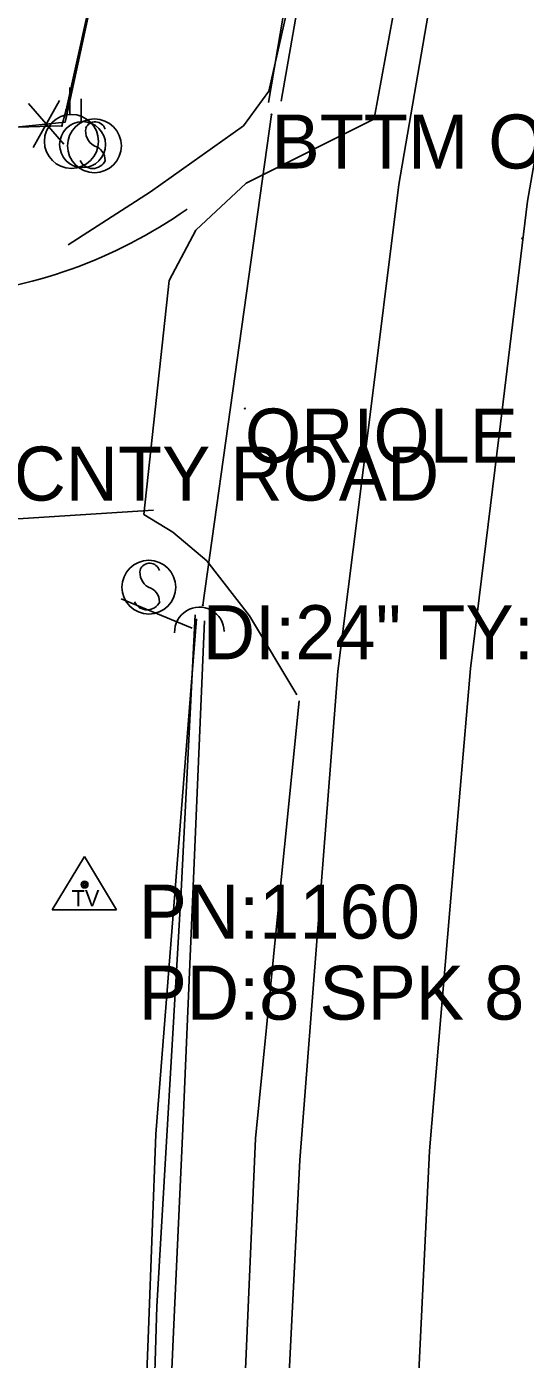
# Model space of a CAD drawing. Extents: x 954793 to 988390, y 1867850 to 1924428.
# Drawn here: x 960952.9 to 960999.1, y 1905465.6 to 1905589 of the extents above; entities that cross this region are included whole.
import ezdxf

# ---------------------------------------------------------------- set-up
doc = ezdxf.new("R2010")
doc.units = 0
for name, color, linetype in [('S_CROSS_DRAIN', 7, 'Continuous'), ('S_DITCHLINE', 7, 'Continuous'), ('S_DRG_PT_SYM', 7, 'Continuous'), ('S_DRIVEWAY', 7, 'Continuous'), ('S_EDGE_PAVEMENT', 7, 'Continuous'), ('S_FENCE', 7, 'Continuous'), ('S_GRAVEL_ROAD', 7, 'Continuous'), ('S_GRD_PT_SYM', 7, 'Continuous'), ('S_MSC_PT_SYM', 7, 'Continuous'), ('S_PAVEMENT_CROWN', 7, 'Continuous'), ('S_SECONDARY_CTL', 7, 'Continuous'), ('S_SECONDARY_CTL_ANNOT', 7, 'Continuous'), ('S_SHOULDER', 7, 'Continuous'), ('S_SIDE_DRAIN', 7, 'Continuous'), ('S_SIDE_DRAIN_ANNOT', 7, 'Continuous'), ('S_SIGN', 7, 'Continuous'), ('S_STREAM', 7, 'Continuous'), ('S_SURVEY_TEXT_ANNOT', 7, 'Continuous'), ('S_UTILITY_POLE', 7, 'Continuous'), ('S_UTL_PT_SYM', 7, 'Continuous')]:
    doc.layers.add(name, color=color, linetype=linetype)

msp = doc.modelspace()

# ---------------------------------------------------------------- linework, layer by layer
at = {"layer": 'S_CROSS_DRAIN'}
msp.add_arc((960968.9, 1905532.93), 2.3, 1.1524, 181.4816, dxfattribs=at)
at = {"layer": 'S_DITCHLINE'}
for points in [[(960975.29, 1905581.95), (960977.49, 1905594.88), (960979.69, 1905607.8), (960982.5, 1905621.27), (960985.31, 1905634.74), (960988.11, 1905648.21), (960990.92, 1905661.68)], [(960976.47, 1905582.09), (960978.64, 1905594.66), (960980.81, 1905607.22), (960983.9, 1905620.71), (960986.99, 1905634.2), (960990.08, 1905647.69), (960993.16, 1905661.18)], [(960962.25, 1905289.04), (960962.35, 1905306.2), (960962.45, 1905323.37), (960962.55, 1905340.53), (960962.65, 1905357.7), (960962.51, 1905371.75), (960962.38, 1905385.8), (960962.24, 1905399.85), (960962.1, 1905413.9), (960962.8, 1905432.03), (960963.49, 1905450.16), (960964.19, 1905468.29), (960964.88, 1905486.43), (960966.76, 1905510.29), (960968.63, 1905534.15)], [(960964.36, 1905253.1), (960964.62, 1905271.14), (960964.88, 1905289.19), (960965.02, 1905306.4), (960965.15, 1905323.62), (960965.29, 1905340.84), (960965.42, 1905358.06), (960965.09, 1905371.99), (960964.76, 1905385.92), (960964.43, 1905399.86), (960964.1, 1905413.79), (960964.91, 1905431.9), (960965.71, 1905450.02), (960966.51, 1905468.14), (960967.32, 1905486.25), (960968.34, 1905510.11), (960969.37, 1905533.98)]]:
    msp.add_lwpolyline(points, dxfattribs=at)
at = {"layer": 'S_DRG_PT_SYM'}
for points in [[(960975.57, 1905580.85), (960975.52, 1905580.85), (960975.57, 1905580.85), (960975.56, 1905580.8), (960975.57, 1905580.85), (960975.62, 1905580.84), (960975.57, 1905580.85), (960975.58, 1905580.9)], [(960975.57, 1905580.85), (960975.52, 1905580.85), (960975.57, 1905580.85), (960975.56, 1905580.8), (960975.57, 1905580.85), (960975.62, 1905580.84), (960975.57, 1905580.85), (960975.58, 1905580.9)], [(960969.22, 1905535.41), (960969.17, 1905535.42), (960969.22, 1905535.41), (960969.22, 1905535.36), (960969.22, 1905535.41), (960969.27, 1905535.4), (960969.22, 1905535.41), (960969.23, 1905535.46)], [(960969.22, 1905535.41), (960969.17, 1905535.42), (960969.22, 1905535.41), (960969.22, 1905535.36), (960969.22, 1905535.41), (960969.27, 1905535.4), (960969.22, 1905535.41), (960969.23, 1905535.46)]]:
    msp.add_lwpolyline(points, close=True, dxfattribs=at)
for points in [[(960975.57, 1905580.85), (960975.57, 1905580.9), (960975.57, 1905580.85), (960975.52, 1905580.85), (960975.57, 1905580.85), (960975.57, 1905580.8), (960975.57, 1905580.85), (960975.62, 1905580.85)], [(960969.22, 1905535.41), (960969.22, 1905535.46), (960969.22, 1905535.41), (960969.17, 1905535.41), (960969.22, 1905535.41), (960969.22, 1905535.36), (960969.22, 1905535.41), (960969.27, 1905535.41)]]:
    msp.add_lwpolyline(points, dxfattribs=at)
at = {"layer": 'S_DRIVEWAY'}
for points in [[(960985.03, 1905580.43), (960973.21, 1905574.49), (960968.57, 1905570.13), (960966.1, 1905565.49)], [(960963.75, 1905543.8), (960966.1, 1905565.49)], [(960977.92, 1905527.11), (960973.54, 1905534.42), (960969.59, 1905539.52), (960966.45, 1905542.18), (960963.75, 1905543.8)]]:
    msp.add_lwpolyline(points, dxfattribs=at)
at = {"layer": 'S_EDGE_PAVEMENT'}
msp.add_lwpolyline([(960977.2, 1905464.29), (960978.18, 1905484.02), (960979.95, 1905506.67), (960981.72, 1905529.31), (960984.53, 1905551.85), (960987.34, 1905574.38), (960991.01, 1905595.74), (960994.41, 1905615.48)], dxfattribs=at)
at = {"layer": 'S_FENCE'}
for p, q in [((960956.37, 1905578.09), (960953.1, 1905581.86)), ((960955.95, 1905582.16), (960953.51, 1905577.79))]:
    msp.add_line(p, q, dxfattribs=at)
for points in [[(960815.04, 1905577.57), (960839.26, 1905577.7), (960885.56, 1905578.77), (960926.55, 1905578.91), (960956.16, 1905579.8), (960956.58, 1905581.28), (960975.1, 1905665.08), (960987.36, 1905722.36), (961010.79, 1905798.2), (961034.06, 1905881.8), (961058.39, 1905965.89), (961080.13, 1906043.62), (961101.12, 1906116.75), (961119.78, 1906176.01), (961127.63, 1906201.88), (961136.16, 1906228.86), (961155.7, 1906295.71), (961179.56, 1906374.8), (961187.71, 1906406.25)], [(960815.04, 1905577.57), (960839.26, 1905577.7), (960885.56, 1905578.77), (960926.55, 1905578.91), (960956.16, 1905579.8), (960956.58, 1905581.28), (960975.1, 1905665.08), (960987.36, 1905722.36), (961010.79, 1905798.2), (961034.06, 1905881.8), (961058.39, 1905965.89), (961080.13, 1906043.62), (961101.12, 1906116.75), (961119.78, 1906176.01), (961127.63, 1906201.88), (961136.16, 1906228.86), (961155.7, 1906295.71), (961179.56, 1906374.8), (961187.71, 1906406.25)], [(960970.12, 1905642.88), (960956.48, 1905580.15), (960929.78, 1905577.41)], [(960960.78, 1905599.92), (960956.53, 1905580.39)]]:
    msp.add_lwpolyline(points, dxfattribs=at)
at = {"layer": 'S_GRAVEL_ROAD'}
msp.add_lwpolyline([(960788.79, 1905550.58), (960841.1, 1905544.31), (960881.85, 1905541.74), (960921.21, 1905541.45), (960964.66, 1905544.21)], dxfattribs=at)
msp.add_ellipse((960942.05, 1905608.46), major_axis=(41.4, 17.04), ratio=0.994492, start_param=4.394232, end_param=4.93593, dxfattribs=at)
at = {"layer": 'S_GRD_PT_SYM'}
msp.add_lwpolyline([(960998.75, 1905569.36), (960998.75, 1905569.41), (960998.75, 1905569.36), (960998.7, 1905569.36), (960998.75, 1905569.36), (960998.75, 1905569.31), (960998.75, 1905569.36), (960998.8, 1905569.36)], dxfattribs=at)
at = {"layer": 'S_MSC_PT_SYM'}
for points in [[(960956.58, 1905581.28), (960956.58, 1905581.33), (960956.58, 1905581.28), (960956.53, 1905581.28), (960956.58, 1905581.28), (960956.58, 1905581.23), (960956.58, 1905581.28), (960956.63, 1905581.28)], [(960956.16, 1905579.8), (960956.16, 1905579.85), (960956.16, 1905579.8), (960956.11, 1905579.8), (960956.16, 1905579.8), (960956.16, 1905579.75), (960956.16, 1905579.8), (960956.21, 1905579.8)], [(960973.11, 1905553.62), (960973.11, 1905553.67), (960973.11, 1905553.62), (960973.06, 1905553.62), (960973.11, 1905553.62), (960973.11, 1905553.57), (960973.11, 1905553.62), (960973.16, 1905553.62)]]:
    msp.add_lwpolyline(points, dxfattribs=at)
for points in [[(960956.58, 1905581.28), (960956.53, 1905581.29), (960956.58, 1905581.28), (960956.57, 1905581.23), (960956.58, 1905581.28), (960956.63, 1905581.26), (960956.58, 1905581.28), (960956.59, 1905581.32)], [(960956.58, 1905581.28), (960956.53, 1905581.29), (960956.58, 1905581.28), (960956.57, 1905581.23), (960956.58, 1905581.28), (960956.63, 1905581.26), (960956.58, 1905581.28), (960956.59, 1905581.32)], [(960956.16, 1905579.8), (960956.11, 1905579.81), (960956.16, 1905579.8), (960956.15, 1905579.75), (960956.16, 1905579.8), (960956.21, 1905579.78), (960956.16, 1905579.8), (960956.17, 1905579.85)], [(960956.16, 1905579.8), (960956.11, 1905579.81), (960956.16, 1905579.8), (960956.15, 1905579.75), (960956.16, 1905579.8), (960956.21, 1905579.78), (960956.16, 1905579.8), (960956.17, 1905579.85)], [(960973.11, 1905553.62), (960973.11, 1905553.67), (960973.11, 1905553.62), (960973.06, 1905553.62), (960973.11, 1905553.62), (960973.11, 1905553.57), (960973.11, 1905553.62), (960973.16, 1905553.62)], [(960973.11, 1905553.62), (960973.11, 1905553.67), (960973.11, 1905553.62), (960973.06, 1905553.62), (960973.11, 1905553.62), (960973.11, 1905553.57), (960973.11, 1905553.62), (960973.16, 1905553.62)]]:
    msp.add_lwpolyline(points, close=True, dxfattribs=at)
at = {"layer": 'S_PAVEMENT_CROWN'}
msp.add_lwpolyline([(960989.18, 1905463.82), (960990.18, 1905484.88), (960992.08, 1905507.22), (960993.97, 1905529.56), (960996.62, 1905551.2), (960999.26, 1905572.83), (961002.88, 1905593.65), (961006.51, 1905614.48), (961010.89, 1905635.22), (961015.28, 1905655.96), (961020.21, 1905676.1), (961025.13, 1905696.23), (961030.14, 1905715.53), (961035.15, 1905734.82), (961040.42, 1905754.54), (961045.69, 1905774.26), (961051.22, 1905794.41)], dxfattribs=at)
at = {"layer": 'S_SECONDARY_CTL'}
for p, q in [((960958.28, 1905512.15), (960955.27, 1905507.2)), ((960958.28, 1905512.15), (960961.23, 1905507.2)), ((960955.27, 1905507.2), (960961.23, 1905507.2))]:
    msp.add_line(p, q, dxfattribs=at)
for radius in [0.311, 0.183, 0.103]:
    msp.add_circle((960958.28, 1905509.54), radius, dxfattribs=at)
at = {"layer": 'S_SHOULDER'}
for points in [[(960985.1, 1905580.64), (960988.48, 1905599.19), (960991.42, 1905615.31)], [(960966.85, 1905238.82), (960967.17, 1905252.72), (960967.48, 1905266.62), (960967.99, 1905288.96), (960968.5, 1905311.3), (960969.14, 1905333.47), (960969.77, 1905355.63), (960970.56, 1905379.53), (960971.34, 1905403.42), (960971.83, 1905424.1), (960972.32, 1905444.78), (960973.2, 1905465.4), (960974.09, 1905486.02), (960976.1, 1905506.29), (960978.12, 1905526.56)]]:
    msp.add_lwpolyline(points, dxfattribs=at)
at = {"layer": 'S_SIDE_DRAIN'}
msp.add_line((960969.22, 1905535.41), (960975.57, 1905580.85), dxfattribs=at)
msp.add_lwpolyline([(960969.22, 1905535.41), (960975.57, 1905580.85)], dxfattribs=at)
msp.add_lwpolyline([(960969.22, 1905535.41), (960975.57, 1905580.85)], dxfattribs=at)
at = {"layer": 'S_SIGN'}
for centre in [(960959.19, 1905577.95), (960964.22, 1905537.08)]:
    msp.add_circle(centre, 2.49, dxfattribs=at)
for centre, radius, start, end in [((960959.87, 1905579.28), 1.5, 167.1196, 241.9813), ((960959.26, 1905579.22), 0.95, 16.5258, 156.8957), ((960958.77, 1905576.61), 1.4, 358.6529, 73.7063), ((960959.03, 1905577.13), 1.28, 204.641, 335.359), ((960964.9, 1905538.41), 1.5, 167.1196, 241.9813), ((960964.29, 1905538.35), 0.95, 16.5258, 156.8957), ((960963.8, 1905535.74), 1.4, 358.6529, 73.7063), ((960964.06, 1905536.26), 1.28, 204.641, 335.359)]:
    msp.add_arc(centre, radius, start, end, dxfattribs=at)
at = {"layer": 'S_STREAM'}
for points in [[(961006.94, 1905709.69), (960999.8, 1905686.08), (960990.78, 1905656.48), (960985.22, 1905630.91), (960977.87, 1905594.37), (960975.31, 1905583.02), (960972.97, 1905579.81), (960964.37, 1905573.68), (960956.75, 1905568.77)], [(960961.65, 1905536), (960968.24, 1905533.29)], [(960968.5, 1905534.51), (960967.21, 1905508.92), (960964.97, 1905470.47), (960963.93, 1905436.95), (960963.93, 1905398.69), (960963.58, 1905346.97), (960963.44, 1905310.79)]]:
    msp.add_lwpolyline(points, dxfattribs=at)
at = {"layer": 'S_UTILITY_POLE'}
for p, q in [((960956.91, 1905580.88), (960956.91, 1905583.36)), ((960957.97, 1905580.2), (960957.97, 1905582.31))]:
    msp.add_line(p, q, dxfattribs=at)
for centre, radius in [((960957.06, 1905578.36), 2.5), ((960958.09, 1905578.06), 2.13)]:
    msp.add_circle(centre, radius, dxfattribs=at)
at = {"layer": 'S_UTL_PT_SYM'}
msp.add_lwpolyline([(960998.75, 1905569.36), (960998.75, 1905569.41), (960998.75, 1905569.36), (960998.7, 1905569.36), (960998.75, 1905569.36), (960998.75, 1905569.31), (960998.75, 1905569.36), (960998.8, 1905569.36)], close=True, dxfattribs=at)
msp.add_lwpolyline([(960998.75, 1905569.36), (960998.75, 1905569.41), (960998.75, 1905569.36), (960998.7, 1905569.36), (960998.75, 1905569.36), (960998.75, 1905569.31), (960998.75, 1905569.36), (960998.8, 1905569.36)], close=True, dxfattribs=at)
msp.add_lwpolyline([(960998.75, 1905569.36), (960998.75, 1905569.41), (960998.75, 1905569.36), (960998.7, 1905569.36), (960998.75, 1905569.36), (960998.75, 1905569.31), (960998.75, 1905569.36), (960998.8, 1905569.36)], dxfattribs=at)

# ---------------------------------------------------------------- texts
at = {"layer": 'S_SECONDARY_CTL'}
msp.add_text('TV', height=1.5, rotation=360, dxfattribs=at).set_placement((960957.08, 1905507.53))
at = {"layer": 'S_SECONDARY_CTL_ANNOT'}
for s, p in [('PN:1160', (960963.28, 1905504.54)), ('PD:8 SPK 8 SPIKE', (960963.28, 1905497.04))]:
    msp.add_text(s, height=5, dxfattribs=at).set_placement(p)
at = {"layer": 'S_SIDE_DRAIN_ANNOT'}
for s, p in [('BTTM OF PIPE CN:60%FILL', (960975.57, 1905575.85)), ('DI:24" TY:CMP CN:30%FILL BTTM O', (960969.22, 1905530.41))]:
    msp.add_text(s, height=5, dxfattribs=at).set_placement(p)
at = {"layer": 'S_SURVEY_TEXT_ANNOT'}
for s, p in [('ORIOLE DR', (960973.11, 1905548.62)), ('GR CNTY ROAD', (960939.82, 1905545.1))]:
    msp.add_text(s, height=5, dxfattribs=at).set_placement(p)

doc.saveas('drawing.dxf')
